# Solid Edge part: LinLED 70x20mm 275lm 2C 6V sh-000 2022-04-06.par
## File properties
Author: robert.pupel
Template: iso metric part.par
Last saved by: robert.pupel
Revision: 1
Application: Solid Edge
Gęstość: 0.000 kg/m^3
Dokładność: 0.990
Username: robert.pupel
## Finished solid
Body 1: solid body, 634 faces, 1618 edges, 1012 vertices.
  Faces by surface: plane 334, cylinder 140, spline 96, cone 30, sphere 16, torus 10, spun 8
  Edges by curve: line 982, curve on surface 324, circle 192, ellipse 66, spline 50, intersection 4
Bounding box of the edges (mm; curved faces can reach further): 20.000 x 4.450 x 69.600, from (-10, -3.45, -34.8) to (10, 1, 34.8).
Cylindrical faces by radius (mm): R0.2 x46, R0.2169 x6, R0.25 x16, R0.3373 x6, R0.4 x8, R0.4006 x2, R0.4008 x2, R0.525 x2, R0.6 x20, R1 x16, R1.1 x4, R1.2 x10, R2.15 x2
Conical faces (half-angle, radius in mm at the cone's reference point): 0.5 deg R0.5056 x4, 0.5 deg R1.0082 x4, 1 deg R0.5511 x2, 10 deg R0.2132 x4, 10 deg R0.4132 x4, 18.8604 deg R1.0669 x4, 27.363 deg R0.6214 x2, 45 deg R0.575 x2, 45 deg R0.625 x4
Toroidal faces (ring radius, tube radius in mm): R0.8 r0.2 x4, R0.8522 r0.3 x2, R0.9002 r0.2 x2, R0.9018 r0.2 x2
Spherical faces by radius (mm): R0.2 x12, R0.6 x4
Planar faces by outward normal: +x 36, +y 9, +z 34, -x 36, -y 49, -z 34, oblique 136
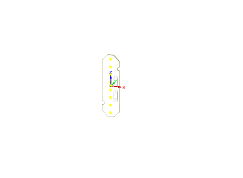
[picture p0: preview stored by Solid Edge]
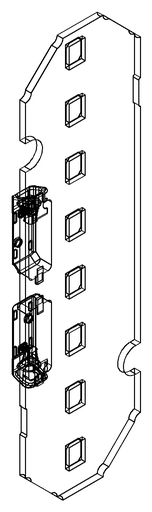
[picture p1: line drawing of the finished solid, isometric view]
